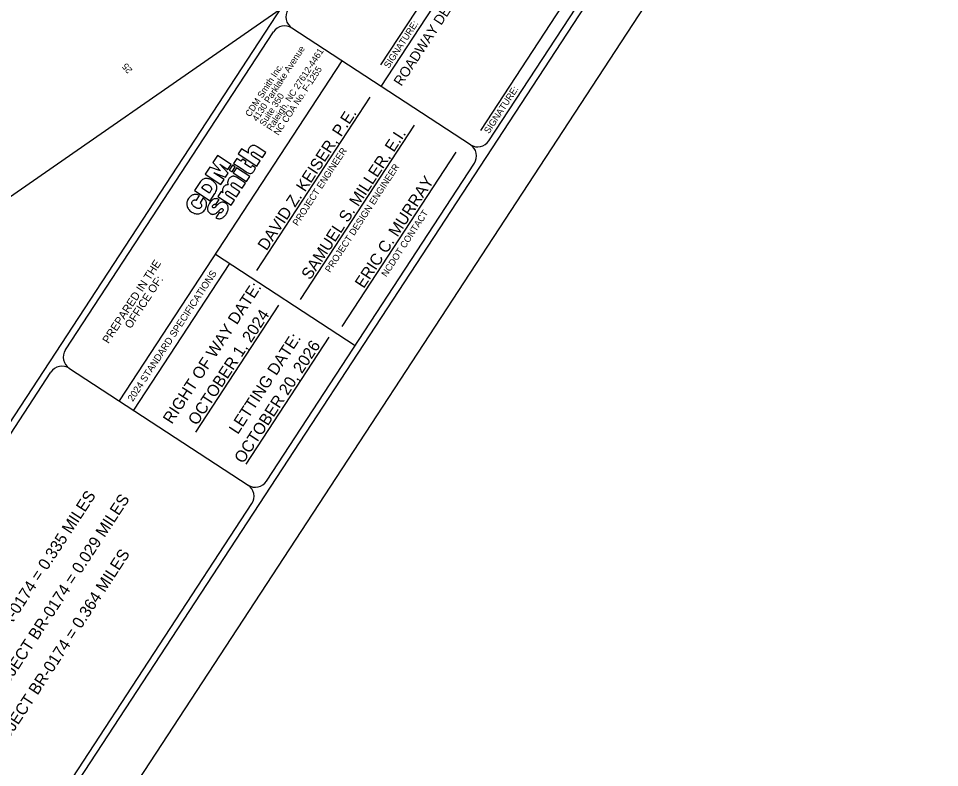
# Model space of a CAD drawing. Extents: x 1190029 to 2382315, y 163128 to 334830.
# Drawn here: x 2380933 to 2382315, y 331527 to 332651 of the extents above; entities that cross this region are included whole.
import ezdxf

# ---------------------------------------------------------------- set-up
doc = ezdxf.new("R2010")
doc.units = 0
for name, color, linetype in [('Exist Property Line', 7, 'Continuous'), ('Exist Utilities Telephone UG FO SUE LOS B Text', 7, 'Continuous'), ('P_NCDOT_Horizontal_Alignment_Curve_and_Spiral_Data', 7, 'Continuous'), ('Sheet_Plan_CELL', 7, 'Continuous'), ('Sheet_RDY_PE_Seal_Cell', 7, 'Continuous'), ('z - Construction', 7, 'Continuous')]:
    doc.layers.add(name, color=color, linetype=linetype)

msp = doc.modelspace()

# ---------------------------------------------------------------- linework, layer by layer
at = {"layer": 'Exist Utilities Telephone UG FO SUE LOS B Text'}
for p, q in [((2380185.5, 330920.1), (2381876.3, 333506.5)), ((2380443.3, 330620.2), (2382199.8, 333307)), ((2381477.2, 332548.7), (2381781.1, 333013.6)), ((2381638.8, 332467), (2381920.8, 332898.4)), ((2381476.5, 332580.9), (2381631.4, 332817.7)), ((2381626.6, 332482.8), (2381781.4, 332719.6)), ((2381611.2, 332461.2), (2381343.3, 332636.3)), ((2381003.7, 332153.4), (2381315.6, 332630.5)), ((2381418.2, 332587.3), (2381084.4, 332076.8)), ((2381290.7, 332272.7), (2381460.5, 332532.4)), ((2381356.3, 332229), (2381527.3, 332490.5)), ((2381418.5, 332188.3), (2381589.5, 332449.9)), ((2381228.4, 332297), (2381438.1, 332159.9)), ((2381249.7, 332283), (2381105.8, 332062.8)), ((2381323.3, 332220.6), (2381198.8, 332030.2)), ((2381208.2, 332219.6), (2381208.2, 332219.6)), ((2381398.4, 332172.5), (2381273.9, 331982)), ((2381009.5, 332125.7), (2381277.4, 331950.6)), ((2381261, 332125.3), (2381261, 332125.3)), ((2380566, 331483.8), (2380981.8, 332119.9))]:
    msp.add_line(p, q, dxfattribs=at)
for points in [[(2381305, 331956.4), (2381617, 332433.5)], [(2380867.3, 331286.8), (2381283.2, 331922.9)]]:
    msp.add_lwpolyline(points, dxfattribs=at)
for centre, start, end in [((2381354.2, 332653.1), 146.8248, 236.8248), ((2381332.3, 332619.6), 56.8248, 146.8248), ((2381622, 332478), 236.8248, 326.8248), ((2381600.1, 332444.5), 326.8248, 56.8248), ((2381020.4, 332142.5), 146.8248, 236.8248), ((2380998.6, 332109), 56.8248, 146.8248), ((2381288.3, 331967.4), 236.8248, 326.8223), ((2381266.4, 331933.9), 326.8248, 56.8248)]:
    msp.add_arc(centre, 20, start, end, dxfattribs=at)
at = {"layer": 'P_NCDOT_Horizontal_Alignment_Curve_and_Spiral_Data'}
for points in [[(2381287.6, 332459.9), (2381286.7, 332460.1), (2381285.9, 332460.2), (2381285.1, 332460.2), (2381284.3, 332460.1), (2381283.5, 332460), (2381282.9, 332459.7), (2381282.2, 332459.3), (2381281.5, 332458.9), (2381280.9, 332458.4), (2381280.3, 332457.8), (2381279.7, 332457.2), (2381279.2, 332456.5), (2381278.6, 332455.5), (2381278.1, 332454.5), (2381277.7, 332453.5), (2381277.5, 332452.3), (2381277.5, 332451.4), (2381277.5, 332450.6), (2381277.7, 332449.6), (2381277.9, 332448.5), (2381267.8, 332455.1), (2381262.7, 332447.4), (2381290.6, 332429.2), (2381295.6, 332436.9), (2381286, 332443.2), (2381284.8, 332444), (2381283.8, 332444.9), (2381283.2, 332445.7), (2381282.9, 332446.1), (2381282.7, 332446.5), (2381282.5, 332447.1), (2381282.5, 332447.8), (2381282.6, 332448.4), (2381282.8, 332448.9), (2381283.3, 332449.6), (2381283.7, 332450), (2381284.2, 332450.2), (2381284.9, 332450.3), (2381285.5, 332450.4), (2381286.3, 332450.1), (2381287.1, 332449.8), (2381288, 332449.2), (2381299, 332442), (2381304, 332449.7), (2381291.3, 332458.1), (2381290.4, 332458.7), (2381289.4, 332459.2), (2381288.5, 332459.6), (2381287.6, 332459.9)], [(2381226.3, 332418.9), (2381226.4, 332419.1), (2381243.6, 332412.4), (2381247.8, 332418.8), (2381234.9, 332432.2), (2381235, 332432.3), (2381247.2, 332424.3), (2381252.1, 332431.8), (2381231.5, 332445.3), (2381224.5, 332434.5), (2381236.1, 332422.1), (2381236.1, 332422), (2381220, 332427.7), (2381213, 332417.1), (2381236.6, 332401.6), (2381241.4, 332409), (2381226.3, 332418.9)], [(2381254.2, 332430.6), (2381249.3, 332423.1), (2381253.4, 332420.5), (2381258.3, 332427.9), (2381254.2, 332430.6)], [(2381268.9, 332439.7), (2381266.7, 332436.4), (2381260.6, 332440.4), (2381255.8, 332433), (2381261.9, 332429.1), (2381267.5, 332425.4), (2381274.5, 332420.8), (2381276, 332419.8), (2381277.5, 332419.1), (2381278.8, 332418.6), (2381280, 332418.3), (2381280.9, 332418.2), (2381281.8, 332418.2), (2381282.5, 332418.5), (2381283.3, 332418.8), (2381284.1, 332419.3), (2381284.9, 332420.1), (2381285.8, 332421), (2381286.6, 332422.3), (2381287.2, 332423.2), (2381287.7, 332424.3), (2381288.3, 332425.5), (2381288.6, 332426.8), (2381283.7, 332430.1), (2381283.5, 332429.7), (2381283.2, 332429.1), (2381282.6, 332427.9), (2381282.2, 332427.5), (2381281.8, 332427.4), (2381281.5, 332427.3), (2381281.3, 332427.3), (2381281, 332427.3), (2381280.5, 332427.5), (2381279.4, 332428.1), (2381272.4, 332432.8), (2381274.5, 332436), (2381268.9, 332439.7)], [(2381260.2, 332426.5), (2381255.3, 332419), (2381275.3, 332405.9), (2381280.2, 332413.4), (2381260.2, 332426.5)], [(2381225, 332406.8), (2381223.7, 332407.6), (2381222.6, 332408.4), (2381221.4, 332409), (2381220.1, 332409.5), (2381218.9, 332410), (2381217.7, 332410.3), (2381216.4, 332410.6), (2381215.2, 332410.7), (2381214, 332410.7), (2381212.7, 332410.5), (2381211.6, 332410.2), (2381210.4, 332409.7), (2381209.2, 332409.1), (2381208.1, 332408.3), (2381206.9, 332407.3), (2381205.9, 332406.1), (2381204.9, 332404.7), (2381197.1, 332392.7), (2381220.7, 332377.3), (2381227.6, 332387.9), (2381228.6, 332389.3), (2381229.3, 332390.9), (2381229.9, 332392.4), (2381230.3, 332393.8), (2381230.5, 332395.1), (2381230.7, 332396.6), (2381230.6, 332397.9), (2381230.4, 332399.1), (2381230, 332400.3), (2381229.5, 332401.5), (2381228.9, 332402.6), (2381228.1, 332403.7), (2381227.2, 332404.8), (2381226.2, 332405.8), (2381225, 332406.8)], [(2381207.9, 332396.1), (2381209.4, 332398.4), (2381210.1, 332399.3), (2381210.7, 332400.1), (2381211.4, 332400.7), (2381212.2, 332401.1), (2381212.9, 332401.4), (2381213.6, 332401.7), (2381214.2, 332401.7), (2381214.8, 332401.8), (2381215.5, 332401.8), (2381216.1, 332401.6), (2381217.3, 332401.3), (2381218.1, 332400.9), (2381218.8, 332400.5), (2381219.6, 332399.9), (2381220.5, 332399.1), (2381221.4, 332398.2), (2381221.7, 332397.6), (2381222, 332397.1), (2381222.3, 332396.5), (2381222.4, 332395.9), (2381222.5, 332395.3), (2381222.5, 332394.6), (2381222.4, 332393.8), (2381222.2, 332393.1), (2381221.8, 332392.3), (2381221.3, 332391.4), (2381219.4, 332388.5), (2381207.9, 332396.1)], [(2381244.9, 332386.2), (2381244.4, 332386.7), (2381244.1, 332387.4), (2381243.9, 332388), (2381243.8, 332388.6), (2381243.9, 332389.3), (2381244.3, 332390.1), (2381244.9, 332390.8), (2381245.5, 332391.3), (2381246.1, 332391.5), (2381246.8, 332391.5), (2381247.5, 332391.3), (2381248.2, 332391.1), (2381248.8, 332390.7), (2381249.6, 332390.2), (2381260.3, 332383.2), (2381265.3, 332390.7), (2381254.5, 332397.8), (2381253.8, 332398.3), (2381253.2, 332398.9), (2381252.7, 332399.4), (2381252.4, 332400.1), (2381252.2, 332400.7), (2381252.1, 332401.3), (2381252.2, 332402), (2381252.6, 332402.8), (2381253.2, 332403.5), (2381253.8, 332404), (2381254.4, 332404.1), (2381255.1, 332404.1), (2381255.8, 332403.9), (2381256.5, 332403.7), (2381257.1, 332403.4), (2381257.9, 332402.9), (2381268.6, 332395.9), (2381273.6, 332403.4), (2381259.9, 332412.4), (2381258.7, 332413.1), (2381258, 332413.4), (2381257.3, 332413.6), (2381256.6, 332413.8), (2381255.9, 332413.9), (2381255.1, 332413.9), (2381254.4, 332413.9), (2381253.6, 332413.7), (2381252.9, 332413.5), (2381252.1, 332413.2), (2381251.4, 332412.8), (2381250.7, 332412.3), (2381250, 332411.6), (2381249.3, 332410.9), (2381248.7, 332409.9), (2381248.1, 332409.1), (2381247.7, 332408.2), (2381247.4, 332407.4), (2381247.1, 332406.6), (2381246.9, 332405.8), (2381246.8, 332405.1), (2381246.8, 332403.9), (2381246.9, 332402.9), (2381247.1, 332402.1), (2381247.4, 332401.2), (2381246.4, 332401.2), (2381245.4, 332401.1), (2381244.5, 332400.8), (2381243.6, 332400.4), (2381242.8, 332399.8), (2381242, 332399.3), (2381241.3, 332398.6), (2381240.7, 332397.8), (2381240.1, 332396.8), (2381239.6, 332395.7), (2381239.3, 332394.7), (2381239, 332393.6), (2381238.9, 332392.5), (2381239, 332391.4), (2381239.2, 332390.4), (2381239.6, 332389.1), (2381236.9, 332390.9), (2381232.1, 332383.6), (2381252, 332370.5), (2381257, 332378.1), (2381246.2, 332385.1), (2381245.5, 332385.7), (2381244.9, 332386.2)], [(2381202.5, 332365.7), (2381201.9, 332365.7), (2381201.3, 332365.9), (2381200, 332366.3), (2381198.7, 332366.9), (2381197.5, 332367.6), (2381196.3, 332368.5), (2381195.3, 332369.4), (2381194.4, 332370.4), (2381194, 332370.9), (2381193.7, 332371.5), (2381193.4, 332372.1), (2381193.2, 332372.7), (2381193.1, 332373.2), (2381193.1, 332373.9), (2381193.1, 332374.5), (2381193.3, 332375.1), (2381193.6, 332375.7), (2381193.9, 332376.4), (2381194.4, 332376.9), (2381194.8, 332377.3), (2381195.1, 332377.6), (2381195.5, 332377.9), (2381196, 332378.2), (2381196.4, 332378.3), (2381197.3, 332378.4), (2381198.1, 332378.4), (2381198.9, 332378.3), (2381199.5, 332378.1), (2381199.9, 332377.9), (2381204.5, 332385), (2381203.4, 332385.5), (2381202.2, 332386), (2381201, 332386.4), (2381199.9, 332386.5), (2381198.8, 332386.7), (2381197.7, 332386.7), (2381196.6, 332386.6), (2381195.6, 332386.3), (2381194.6, 332386), (2381193.5, 332385.6), (2381192.6, 332385), (2381191.7, 332384.3), (2381190.7, 332383.5), (2381189.9, 332382.6), (2381189, 332381.6), (2381188.2, 332380.4), (2381187.3, 332379.1), (2381186.7, 332377.6), (2381186.2, 332376.3), (2381185.8, 332374.9), (2381185.6, 332373.5), (2381185.6, 332372.2), (2381185.7, 332370.8), (2381185.9, 332369.5), (2381186.3, 332368.2), (2381186.7, 332367), (2381187.4, 332365.7), (2381188.2, 332364.5), (2381189.1, 332363.4), (2381190.2, 332362.3), (2381191.4, 332361.3), (2381192.7, 332360.3), (2381194, 332359.5), (2381195.4, 332358.9), (2381196.8, 332358.3), (2381198.1, 332357.9), (2381199.5, 332357.7), (2381200.8, 332357.5), (2381202.2, 332357.5), (2381203.6, 332357.6), (2381204.9, 332357.9), (2381206.2, 332358.5), (2381207.4, 332359), (2381208.6, 332359.7), (2381209.7, 332360.6), (2381210.9, 332361.7), (2381211.9, 332362.9), (2381212.9, 332364.2), (2381213.7, 332365.4), (2381214.3, 332366.8), (2381214.8, 332368.1), (2381215, 332369.4), (2381215.3, 332370.6), (2381215.3, 332371.9), (2381215.3, 332373), (2381215, 332374.2), (2381214.7, 332375.4), (2381214.4, 332376.4), (2381213.8, 332377.4), (2381213.2, 332378.4), (2381212.6, 332379.3), (2381211.8, 332380.1), (2381211.1, 332380.8), (2381210.2, 332381.4), (2381205.5, 332374.3), (2381206.2, 332373.6), (2381206.8, 332372.9), (2381207.2, 332372.1), (2381207.6, 332371.3), (2381207.7, 332370.4), (2381207.7, 332369.7), (2381207.4, 332368.8), (2381206.9, 332367.8), (2381206.5, 332367.3), (2381206, 332366.8), (2381205.5, 332366.4), (2381205, 332366.1), (2381204.4, 332365.8), (2381203.8, 332365.7), (2381203.2, 332365.7), (2381202.5, 332365.7)], [(2381242.7, 332374.1), (2381242, 332374.5), (2381241.3, 332374.7), (2381240.6, 332374.9), (2381239.9, 332375), (2381239.3, 332375.1), (2381238.6, 332375.1), (2381238, 332375), (2381236.7, 332374.7), (2381235.5, 332374.2), (2381234.5, 332373.7), (2381233.4, 332372.9), (2381232.4, 332372), (2381231.4, 332371.2), (2381229.6, 332369.4), (2381228.1, 332367.8), (2381227.4, 332367.3), (2381226.7, 332366.8), (2381226.4, 332366.6), (2381225.9, 332366.4), (2381225.4, 332366.4), (2381224.9, 332366.6), (2381224.4, 332367.1), (2381224.1, 332367.5), (2381223.9, 332367.9), (2381223.9, 332368.4), (2381224, 332368.9), (2381224.3, 332369.4), (2381224.8, 332370.4), (2381225.1, 332370.8), (2381225.5, 332371.2), (2381226, 332371.5), (2381226.6, 332371.7), (2381227.2, 332371.9), (2381227.8, 332371.9), (2381228.4, 332371.8), (2381229, 332371.5), (2381234, 332379), (2381232.8, 332379.7), (2381231.7, 332380.1), (2381230.6, 332380.3), (2381229.5, 332380.4), (2381228.5, 332380.3), (2381227.5, 332380.2), (2381226.5, 332379.9), (2381225.6, 332379.4), (2381224.7, 332378.9), (2381223.8, 332378.2), (2381223, 332377.6), (2381222.2, 332376.8), (2381221.4, 332376), (2381220.8, 332375.2), (2381219.5, 332373.4), (2381218.5, 332371.7), (2381218.1, 332370.7), (2381217.6, 332369.8), (2381217.3, 332368.7), (2381217, 332367.8), (2381216.8, 332366.8), (2381216.6, 332365.7), (2381216.7, 332364.7), (2381216.7, 332363.6), (2381217, 332362.6), (2381217.3, 332361.7), (2381217.9, 332360.8), (2381218.6, 332359.9), (2381219.4, 332359), (2381220.4, 332358.2), (2381221.2, 332357.8), (2381222, 332357.4), (2381222.7, 332357.1), (2381223.5, 332357), (2381224.2, 332356.8), (2381225.1, 332356.9), (2381225.8, 332357), (2381226.6, 332357.1), (2381227.4, 332357.4), (2381228.2, 332357.8), (2381229.1, 332358.3), (2381229.9, 332358.8), (2381230.8, 332359.5), (2381231.8, 332360.3), (2381233.7, 332362.2), (2381235.7, 332364.2), (2381236.5, 332364.9), (2381237.1, 332365.3), (2381237.7, 332365.5), (2381238.2, 332365.5), (2381238.7, 332365.4), (2381239.2, 332365.2), (2381239.6, 332364.8), (2381239.9, 332364.3), (2381240, 332363.7), (2381240, 332363.2), (2381239.9, 332362.7), (2381239.7, 332362.1), (2381239.2, 332361.1), (2381238.7, 332360.5), (2381238.2, 332359.9), (2381237.6, 332359.6), (2381237.1, 332359.3), (2381236.4, 332359.2), (2381235.6, 332359.3), (2381235, 332359.4), (2381234.3, 332359.8), (2381229.1, 332351.8), (2381230.3, 332351.2), (2381231.5, 332350.7), (2381232.6, 332350.5), (2381233.7, 332350.3), (2381234.8, 332350.3), (2381235.9, 332350.5), (2381237, 332350.7), (2381237.9, 332351.1), (2381238.9, 332351.6), (2381239.9, 332352.2), (2381240.8, 332352.9), (2381241.6, 332353.6), (2381242.5, 332354.4), (2381243.2, 332355.3), (2381243.9, 332356.2), (2381244.6, 332357.1), (2381245.9, 332359.2), (2381246.3, 332360.3), (2381246.8, 332361.3), (2381247.2, 332362.4), (2381247.4, 332363.5), (2381247.7, 332364.6), (2381247.7, 332365.8), (2381247.8, 332366.9), (2381247.6, 332367.9), (2381247.3, 332369), (2381246.9, 332370), (2381246.2, 332371), (2381245.5, 332371.9), (2381244.6, 332372.9), (2381243.4, 332373.6), (2381242.7, 332374.1)]]:
    msp.add_lwpolyline(points, dxfattribs=at)
at = {"layer": 'Sheet_Plan_CELL'}
msp.add_lwpolyline([(2380382.5, 332802.6), (2381396.3, 333506.5), (2381643.5, 333150.4), (2381325.8, 332664.3), (2380871.9, 332349.2)], close=True, dxfattribs=at)
at = {"layer": 'z - Construction'}
msp.add_line((2380454, 330499.6), (2382314.5, 333345.4), dxfattribs=at)

# ---------------------------------------------------------------- texts
at = {"layer": 'Exist Property Line'}
msp.add_text('25', height=10, rotation=129.5852, dxfattribs=at).set_placement((2381104.7, 332573.2))
at = {"layer": 'Exist Utilities Telephone UG FO SUE LOS B Text'}
for s, height, p in [('ROADWAY DESIGN ENGINEER', 14.999, (2381507.3, 332548.1)), ('SIGNATURE:', 10, (2381488.7, 332575)), ('SIGNATURE:', 10, (2381638.8, 332476.9)), ('PROJECT ENGINEER', 9.999, (2381351.8, 332338.8)), ('PROJECT DESIGN ENGINEER', 9.999, (2381400.4, 332268.7)), ('NCDOT CONTACT', 9.999, (2381484.9, 332262.1)), ('2024 STANDARD SPECIFICATIONS', 10.4, (2381104.6, 332075.1)), ('RIGHT OF WAY DATE: ', 17.5, (2381163.1, 332041)), ('LETTING DATE:', 17.5, (2381262.1, 332025.6))]:
    msp.add_text(s, height=height, rotation=56.8248, dxfattribs=at).set_placement(p)
at = {"layer": 'P_NCDOT_Horizontal_Alignment_Curve_and_Spiral_Data'}
for s, p in [('4130 Parklake Avenue', (2381291.2, 332495.3)), ('Raleigh, NC 27612-4461', (2381312.5, 332481.3)), ('CDM Smith Inc.', (2381280.5, 332502.2)), ('NC COA No. F-1255', (2381323.2, 332474.3)), ('Suite 350', (2381301.9, 332488.3))]:
    msp.add_text(s, height=9.79, rotation=56.8366, dxfattribs=at).set_placement(p)
at = {"layer": 'Sheet_Plan_CELL'}
for s, p in [('    DAVID Z. KEISER, P.E.   ', (2381291, 332279.4)), ('   SAMUEL S. MILLER, E.I.  ', (2381360, 332241.1)), ('      ERIC C. MURRAY      ', (2381429.6, 332211.9)), ('  OCTOBER 1, 2024 ', (2381193.6, 332028.1)), ('OCTOBER 20, 2026 ', (2381270, 331981.8)), ('LENGTH OF ROADWAY PROJECT BR-0174 = 0.335 MILES', (2380700.8, 331401.1)), ('LENGTH OF STRUCTURE PROJECT BR-0174 = 0.029 MILES', (2380738.7, 331376.3)), ('TOTAL LENGTH OF PROJECT BR-0174 = 0.364 MILES', (2380776.7, 331351.5))]:
    msp.add_text(s, height=17.5, rotation=56.8248, dxfattribs=at).set_placement(p)
at = {"layer": 'Sheet_RDY_PE_Seal_Cell'}
for s, p in [('PREPARED IN THE ', (2381068.1, 332161.9)), ('OFFICE OF:', (2381101.5, 332184.3))]:
    msp.add_text(s, height=12, rotation=56.8248, dxfattribs=at).set_placement(p)

doc.saveas('drawing.dxf')
